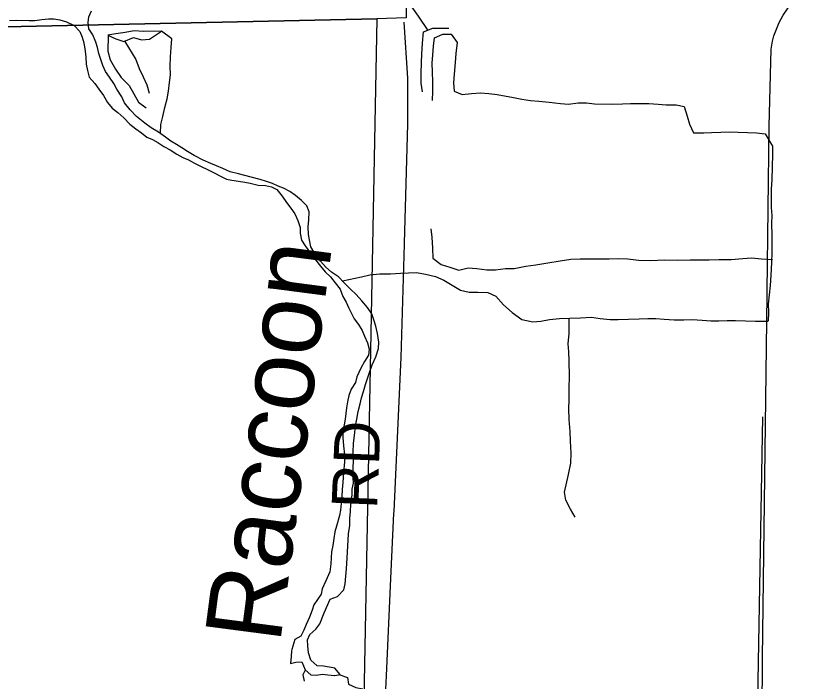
# Model space of a CAD drawing. Extents: x 0 to 34, y 0 to 22.
# Drawn here: x 2.5423 to 3.0351, y 15.0235 to 15.4381 of the extents above; entities that cross this region are included whole.
import ezdxf

# ---------------------------------------------------------------- set-up
doc = ezdxf.new("R2010")
doc.units = 0
for name, color, linetype in [('GM_X_Corporation', 7, 'Continuous'), ('GM_X_Minor_River', 7, 'Continuous'), ('GM_X_Minor_River_Text', 7, 'Continuous'), ('GM_X_Township_Road', 7, 'Continuous'), ('GM_X_Township_Road_Text', 7, 'Continuous')]:
    doc.layers.add(name, color=color, linetype=linetype)

msp = doc.modelspace()

# ---------------------------------------------------------------- linework, layer by layer
at = {"layer": 'GM_X_Corporation'}
for points in [[(2.28152, 15.93664), (2.79079, 15.94235), (2.78571, 15.43693), (2.76751, 15.43626), (2.27529, 15.42554)], [(2.76751, 15.43626), (2.75917, 15.00116), (2.25879, 14.98955), (2.26391, 15.42579), (2.27529, 15.42554)]]:
    msp.add_lwpolyline(points, close=True, dxfattribs=at)
at = {"layer": 'GM_X_Minor_River'}
msp.add_line((2.98799, 14.1), (3.0082, 15.18816), dxfattribs=at)
for points in [[(2.73454, 15.5461), (2.73724, 15.54089), (2.74105, 15.53489), (2.74448, 15.52852), (2.74697, 15.52256), (2.75116, 15.51655), (2.75441, 15.51076), (2.75764, 15.5042), (2.75977, 15.49901), (2.76322, 15.4934), (2.76612, 15.48838), (2.76843, 15.48299), (2.77094, 15.47779), (2.77438, 15.4718), (2.77632, 15.46662), (2.77957, 15.46083), (2.78338, 15.45464), (2.7857, 15.44944), (2.78969, 15.44286), (2.79315, 15.43782), (2.79916, 15.42907)], [(2.75418, 15.18266), (2.75487, 15.18682), (2.75576, 15.19155), (2.75704, 15.19626), (2.7579, 15.20003), (2.75916, 15.20399), (2.76042, 15.20832), (2.7627, 15.21528), (2.76456, 15.22055), (2.7668, 15.22561), (2.76846, 15.23089), (2.76857, 15.23468), (2.76778, 15.24021), (2.76677, 15.24461), (2.76555, 15.24864), (2.76433, 15.25247), (2.7616, 15.25635), (2.75811, 15.26044), (2.75461, 15.26434), (2.7511, 15.26767), (2.74704, 15.27178), (2.74354, 15.27549), (2.73925, 15.27846), (2.73554, 15.28142), (2.73223, 15.28513), (2.72912, 15.28939), (2.72622, 15.29423), (2.72539, 15.29843), (2.72492, 15.30186), (2.72468, 15.30662), (2.72499, 15.31098), (2.72513, 15.31592), (2.72372, 15.31976), (2.7204, 15.32308), (2.71669, 15.32604), (2.71316, 15.32861), (2.70923, 15.33081), (2.70585, 15.33205), (2.70229, 15.33367), (2.69872, 15.33492), (2.69477, 15.33617), (2.68911, 15.33766), (2.68515, 15.33854), (2.6812, 15.3396), (2.67592, 15.34089), (2.67142, 15.34292), (2.66748, 15.34456), (2.66391, 15.34599), (2.65904, 15.34822), (2.65361, 15.35104), (2.64932, 15.35363), (2.64578, 15.35582), (2.64242, 15.35782), (2.63906, 15.36), (2.63572, 15.36257), (2.63124, 15.36555), (2.62677, 15.36834), (2.62267, 15.37112), (2.61748, 15.37545), (2.61361, 15.37955), (2.61012, 15.38383), (2.60833, 15.38768), (2.60524, 15.39233), (2.60345, 15.39599), (2.60071, 15.39987), (2.59834, 15.40336), (2.59655, 15.40721), (2.59533, 15.41085), (2.59411, 15.41469), (2.59326, 15.41832), (2.59222, 15.42177), (2.59026, 15.4262), (2.5879, 15.43006), (2.58744, 15.43388), (2.58792, 15.43747), (2.58955, 15.44123)], [(2.53831, 15.43529), (2.54268, 15.43536), (2.55064, 15.43513), (2.55425, 15.43521), (2.55845, 15.43585), (2.56264, 15.4363), (2.56605, 15.4362), (2.56983, 15.43552), (2.57398, 15.43446), (2.57865, 15.43204), (2.58234, 15.42832), (2.58376, 15.42486), (2.5848, 15.42122), (2.5856, 15.41607), (2.58588, 15.41245), (2.58613, 15.40808), (2.58697, 15.40406), (2.58799, 15.39985), (2.59167, 15.39595), (2.59404, 15.39246), (2.59696, 15.38839), (2.5995, 15.38413), (2.60244, 15.38063), (2.60597, 15.37787), (2.60967, 15.37453), (2.61335, 15.37062), (2.61707, 15.36767), (2.6206, 15.3651), (2.62394, 15.36253), (2.62751, 15.3611), (2.63087, 15.3591), (2.6346, 15.35671), (2.63852, 15.35451), (2.64282, 15.35192), (2.64656, 15.34991), (2.64993, 15.34829), (2.65367, 15.34629), (2.65798, 15.34426), (2.66191, 15.34225), (2.6664, 15.34003), (2.66995, 15.33821), (2.6737, 15.3364), (2.6771, 15.33573), (2.68125, 15.33504), (2.68504, 15.33455), (2.68843, 15.33388), (2.69352, 15.3326), (2.69807, 15.33228), (2.70166, 15.3316), (2.70502, 15.3298)], [(2.7958, 15.39082), (2.795, 15.39616), (2.79499, 15.40225), (2.79537, 15.40907), (2.79552, 15.4142), (2.7959, 15.42103), (2.79648, 15.42804), (2.80243, 15.43034), (2.81231, 15.43043)], [(2.6, 15.42591), (2.59965, 15.41605), (2.60121, 15.41068), (2.60446, 15.40489), (2.60811, 15.39965), (2.6129, 15.39477), (2.61598, 15.38955), (2.61887, 15.38434), (2.6237, 15.38078)], [(2.63325, 15.42857), (2.62164, 15.42833), (2.61615, 15.42868), (2.61061, 15.4277), (2.60471, 15.42692), (2.59975, 15.42611), (2.60461, 15.42369), (2.60969, 15.42203), (2.61565, 15.42451), (2.62074, 15.42323), (2.62569, 15.42365)], [(2.62569, 15.42365), (2.63325, 15.42857)], [(2.63256, 15.36494), (2.63271, 15.37045), (2.63399, 15.37535), (2.63529, 15.38101), (2.63677, 15.38629), (2.63748, 15.39121), (2.6382, 15.39651), (2.63872, 15.40143), (2.63849, 15.40676), (2.63885, 15.41264), (2.6392, 15.41833), (2.63955, 15.42383), (2.63325, 15.42857)], [(2.8021, 15.38532), (2.80227, 15.39121), (2.80224, 15.3971), (2.80203, 15.40299), (2.802, 15.40869), (2.80234, 15.41381), (2.80268, 15.41912), (2.8034, 15.42442), (2.80859, 15.42674), (2.81372, 15.42659), (2.81756, 15.42154), (2.8166, 15.41454), (2.81625, 15.40904), (2.81567, 15.40184), (2.81513, 15.39634), (2.81555, 15.3912), (2.82062, 15.38916), (2.82652, 15.38975), (2.83204, 15.39016), (2.83734, 15.38962), (2.84245, 15.3891), (2.85265, 15.38728), (2.85775, 15.38619), (2.86323, 15.38527), (2.86853, 15.38493), (2.87478, 15.38437), (2.88197, 15.3834), (2.88689, 15.38307), (2.89299, 15.38384), (2.89812, 15.38388), (2.90323, 15.38336), (2.91404, 15.38304), (2.92069, 15.38323), (2.92563, 15.38347), (2.93703, 15.38352), (2.9429, 15.38316), (2.94782, 15.38264), (2.95409, 15.38265), (2.95899, 15.38156), (2.96091, 15.37561), (2.96248, 15.37063), (2.96479, 15.36524), (2.97125, 15.36525), (2.97619, 15.36548), (2.98189, 15.36551), (2.98721, 15.36574), (3.00409, 15.36525), (3.00957, 15.36452), (3.01411, 15.35698), (3.01415, 15.35185), (3.0137, 15.3359), (3.01334, 15.33022), (3.01338, 15.32471), (3.01339, 15.31862), (3.01363, 15.31368), (3.01349, 15.30874), (3.01366, 15.30133), (3.01369, 15.29582), (3.01372, 15.28993), (3.01357, 15.28499), (3.01324, 15.27987), (3.01258, 15.27001), (3.01203, 15.26414), (3.01149, 15.25846), (3.01154, 15.25352), (3.01138, 15.24782)], [(2.61029, 15.4222), (2.61716, 15.41098), (2.61928, 15.40522), (2.62179, 15.40002), (2.62411, 15.39501), (2.62548, 15.38984)], [(2.70502, 15.3298), (2.70833, 15.32571), (2.71106, 15.32183), (2.71381, 15.31833), (2.71636, 15.31465), (2.71815, 15.31061), (2.71954, 15.3062), (2.71963, 15.30259), (2.72046, 15.29838), (2.72282, 15.29471), (2.72611, 15.29024), (2.72922, 15.28597), (2.73233, 15.28208), (2.73527, 15.27858), (2.7386, 15.27544), (2.74153, 15.27175), (2.74446, 15.26786), (2.74622, 15.26325), (2.74821, 15.25959), (2.75, 15.25593), (2.75323, 15.24937), (2.75598, 15.24568), (2.75834, 15.24201), (2.75976, 15.23855), (2.76154, 15.23432), (2.76256, 15.2303), (2.76227, 15.2267), (2.75968, 15.22259), (2.75748, 15.21847), (2.75486, 15.21323), (2.75419, 15.20964), (2.75141, 15.20535), (2.74997, 15.2014), (2.7491, 15.19763), (2.74842, 15.19385), (2.74766, 15.18684), (2.74698, 15.18325), (2.7463, 15.17928), (2.74619, 15.1753), (2.74661, 15.17015), (2.74721, 15.16463), (2.74728, 15.16025), (2.7467, 15.15343), (2.74615, 15.14718), (2.74583, 15.14282), (2.74552, 15.13865), (2.74521, 15.13429), (2.74471, 15.13012), (2.74405, 15.12672), (2.74234, 15.12012), (2.74129, 15.11654), (2.7406, 15.11238), (2.73991, 15.10803), (2.73922, 15.10406), (2.73882, 15.09667), (2.73811, 15.09156), (2.73567, 15.08593), (2.73344, 15.08105), (2.73278, 15.07765), (2.72822, 15.07114), (2.72718, 15.06775), (2.72535, 15.06343), (2.72331, 15.05874), (2.72188, 15.05517), (2.72007, 15.05142), (2.7164, 15.04944), (2.71444, 15.04327)], [(2.80115, 15.30537), (2.80176, 15.30022), (2.80214, 15.29337), (2.80234, 15.28709), (2.80754, 15.28314), (2.813, 15.28147), (2.81864, 15.27959), (2.82438, 15.28114), (2.82968, 15.28061), (2.83611, 15.27985), (2.84143, 15.27989), (2.84772, 15.28066), (2.85303, 15.28069), (2.86029, 15.282), (2.86658, 15.28296), (2.87402, 15.28427), (2.88164, 15.28538), (2.88832, 15.28651), (2.89421, 15.28672), (2.90067, 15.28673), (2.90579, 15.28677), (2.91225, 15.28677), (2.91813, 15.2868), (2.92402, 15.28663), (2.93064, 15.28586), (2.93804, 15.28565), (2.94678, 15.28597), (2.95475, 15.28593), (2.96273, 15.28608), (2.96899, 15.28609), (2.97469, 15.28611), (2.98058, 15.28632), (2.98836, 15.28629), (2.99559, 15.28684), (3.00111, 15.28725), (3.00717, 15.2867), (3.01418, 15.28631)], [(2.74596, 15.27292), (2.75796, 15.27545), (2.76312, 15.27664), (2.76922, 15.27741), (2.77586, 15.27741), (2.78214, 15.2778), (2.78708, 15.27803), (2.79221, 15.27808), (2.79769, 15.27716), (2.80391, 15.27565), (2.80916, 15.27341), (2.81439, 15.27022), (2.81962, 15.26722), (2.82509, 15.26592), (2.8304, 15.26596), (2.83666, 15.26578), (2.84153, 15.26336), (2.8465, 15.25808), (2.85187, 15.25318), (2.85782, 15.24883), (2.86462, 15.24749), (2.86976, 15.24791), (2.8751, 15.2489), (2.88138, 15.24948), (2.88746, 15.24968), (2.89449, 15.24986), (2.90134, 15.25023), (2.90663, 15.24951), (2.91288, 15.24895), (2.918, 15.2488), (2.92427, 15.249), (2.93092, 15.24919), (2.93643, 15.24941), (2.94137, 15.24946), (2.94668, 15.24912), (2.95274, 15.24856), (2.95881, 15.24858), (2.96394, 15.24881), (2.9702, 15.24844), (2.97569, 15.24809), (2.98063, 15.24795), (2.98576, 15.24818), (2.99107, 15.24822), (3.00359, 15.24785), (3.01114, 15.24782)], [(2.89114, 15.12571), (2.88825, 15.13073), (2.88518, 15.13633), (2.88437, 15.14129), (2.88697, 15.15224), (2.8883, 15.15923), (2.88867, 15.16549), (2.88813, 15.1731), (2.88792, 15.179), (2.88738, 15.18661), (2.88719, 15.19346), (2.88734, 15.19858), (2.88737, 15.20637), (2.88757, 15.21339), (2.88727, 15.22309), (2.88705, 15.22861), (2.88682, 15.23374), (2.88738, 15.24019), (2.88734, 15.24968)], [(2.74107, 15.02709), (2.74121, 15.02707), (2.74464, 15.02754), (2.74115, 15.03163), (2.73775, 15.0323), (2.73416, 15.03278), (2.73018, 15.03309), (2.72629, 15.03662), (2.7249, 15.04121), (2.72445, 15.04541), (2.72418, 15.04921), (2.72561, 15.05259), (2.72931, 15.05591), (2.73187, 15.05925), (2.73453, 15.06601), (2.73839, 15.07464), (2.7428, 15.07622), (2.7469, 15.08029), (2.74758, 15.08407), (2.7481, 15.08899), (2.74842, 15.09354), (2.74899, 15.10036), (2.74949, 15.11137), (2.7498, 15.11535), (2.75051, 15.12046), (2.75064, 15.12501), (2.75094, 15.12899), (2.75127, 15.13392), (2.75201, 15.1396), (2.75211, 15.14321), (2.75278, 15.1468), (2.75269, 15.15041), (2.75265, 15.15554), (2.75282, 15.16161), (2.75276, 15.16618), (2.75292, 15.17168), (2.75368, 15.1785), (2.75418, 15.18266)], [(2.71444, 15.04327), (2.71431, 15.04247), (2.71402, 15.03887), (2.71351, 15.03452), (2.71695, 15.03537), (2.72056, 15.03545), (2.7227, 15.03045), (2.72622, 15.0275), (2.72963, 15.02721), (2.73345, 15.02786), (2.73685, 15.02738), (2.74107, 15.02709)], [(2.7227, 15.03029), (2.72136, 15.02737), (2.72214, 15.02339)], [(2.74433, 15.0275), (2.74908, 15.02577), (2.74986, 15.0216), (2.75423, 15.01952), (2.75879, 15.01878)]]:
    msp.add_lwpolyline(points, dxfattribs=at)
at = {"layer": 'GM_X_Township_Road'}
for points in [[(3.01075, 15.26639), (3.01204, 15.36938), (3.01324, 15.41731), (3.01405, 15.42224), (3.01503, 15.42566), (3.01698, 15.43078), (3.01834, 15.434), (3.02085, 15.43854), (3.02355, 15.44251), (3.02586, 15.44572), (3.02684, 15.44837), (3.02803, 15.4535), (3.03446, 15.58947), (3.03464, 15.59325), (3.03514, 15.60656)], [(2.78468, 15.2964), (2.78681, 15.37063), (2.7867, 15.39936), (2.78454, 15.43419)], [(2.77818, 15.12942), (2.78263, 15.22515), (2.78466, 15.29591), (2.78468, 15.2964)], [(2.99365, 14.1), (3.00627, 14.76044), (3.00787, 15.03787), (3.01072, 15.26401), (3.01075, 15.26639)], [(2.75268, 14.74948), (2.75297, 14.81571), (2.7518, 14.91159), (2.75103, 14.93157), (2.7521, 14.94431), (2.77199, 14.99775), (2.7734, 15.02684), (2.77624, 15.08749), (2.77812, 15.12795), (2.77818, 15.12942)]]:
    msp.add_lwpolyline(points, dxfattribs=at)

# ---------------------------------------------------------------- texts
at = {"layer": 'GM_X_Minor_River_Text'}
msp.add_text('Raccoon', height=0.04738, rotation=82.5486, dxfattribs=at).set_placement((2.70707, 15.04638))
at = {"layer": 'GM_X_Township_Road_Text'}
msp.add_text('RD', height=0.028409, rotation=87.5313, dxfattribs=at).set_placement((2.76754, 15.13038))

doc.saveas('drawing.dxf')
